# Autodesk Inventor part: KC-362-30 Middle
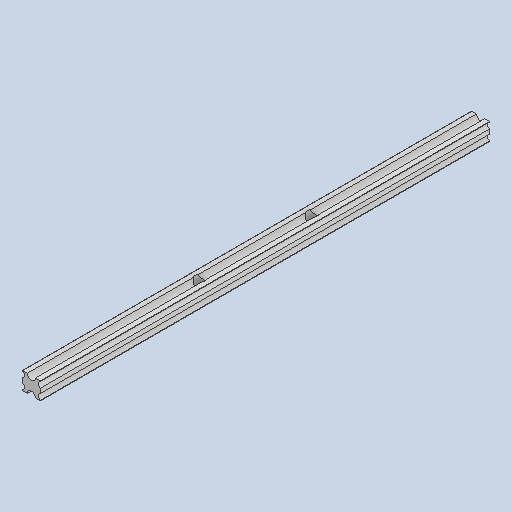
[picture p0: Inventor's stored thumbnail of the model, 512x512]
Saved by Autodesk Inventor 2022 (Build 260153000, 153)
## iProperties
Created: 2021-09
Part Number: KC-362-30 Middle
Material: Generic
Document SubType Name: Modeling
Designer: deli
Density: 1 g/cm^3
Appearance: Default
Author: deli
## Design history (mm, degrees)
sketch "Sketch1"
  geometry: L1 (12, 5.8)-(8.75, 5.8) reference; L2 (3.25, 5.8)-(0, 5.8) reference; L3 (0, 1.52)-(0, -1.52) reference; L4 (0, -5.8)-(3.25, -5.8) reference; L5 (8.75, -5.8)-(12, -5.8) reference; L6 (12, -5.8)-(12, -5.48) reference; L7 (12, -1.52)-(12, 1.52) reference; L8 (12, 5.48)-(12, 5.8) reference; L9 (0, 5.8)-(0, 5.48) reference; L10 (0, -5.48)-(0, -5.8) reference; A1 r 2.75 centre (6, 5.8) between (3.25, 5.8) and (8.75, 5.8) reference; A2 r 2.1 centre (-0.7, 3.5) between (0, 1.52) and (0, 5.48) reference; A3 r 2.1 centre (-0.7, -3.5) between (0, -5.48) and (0, -1.52) reference; A4 r 2.75 centre (6, -5.8) between (8.75, -5.8) and (3.25, -5.8) reference; A5 r 2.1 centre (12.7, -3.5) between (12, -1.52) and (12, -5.48) reference; A6 r 2.1 centre (12.7, 3.5) between (12, 5.48) and (12, 1.52) reference; 1 further point
extrude "Extrusion1" new body sketch "Sketch1" distance "d0" = 300; taper "d1" = 0 deg
sketch "Sketch2"
  geometry: C1 r 3.25 at (-6, 187.5); C2 r 3.25 at (-6, 112.5); A1 r 3.25 centre (-6, 187.5) between (-8.75, 189.232) and (-8.75, 185.768) reference; A2 r 3.25 centre (-6, 112.5) between (-8.75, 114.232) and (-8.75, 110.768) reference; 5 further points
  constraints: 2 centre point, 2 coincident, 2 concentric
extrude "Extrusion2" cut sketch "Sketch2" distance "d2" = 300; taper "d3" = 0 deg
body "Solid1"
node "Reference1"
node "Reference2"
node "Reference3"
node "Reference4"
node "Reference5"
node "Reference6"
node "Reference7"
node "Reference8"
node "Reference9"
node "Reference10"
node "Reference11"
node "Reference12"
node "Reference13"
node "Reference14"
node "Reference15"
node "Reference16"
node "Reference17"
node "Reference18"
